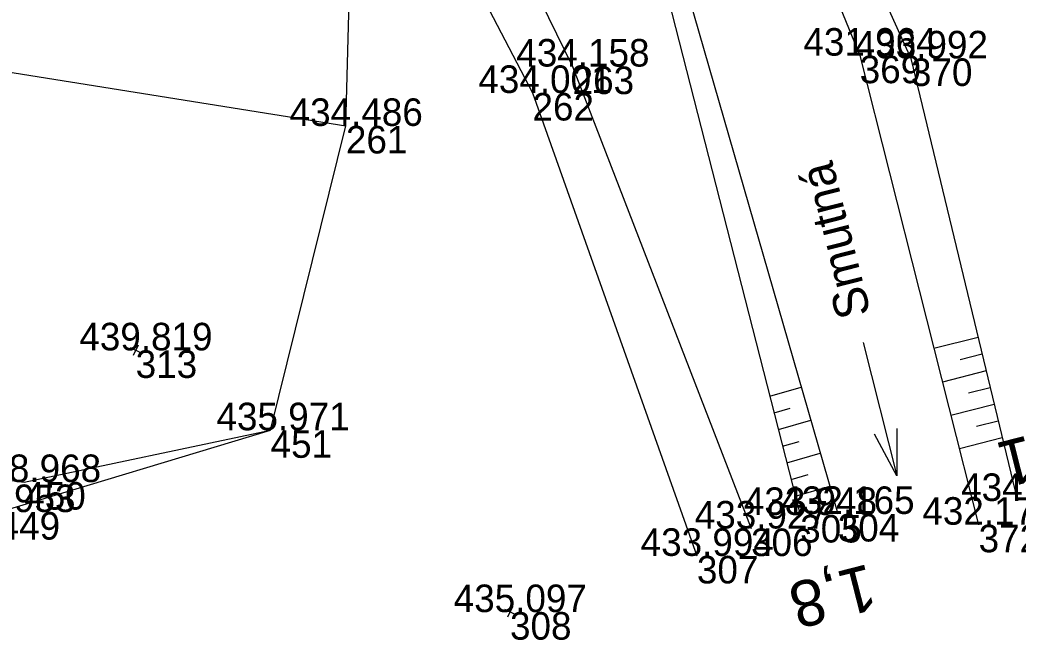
# Model space of a CAD drawing. Extents: x -751615 to -750797, y -1114905 to -1114561.
# Drawn here: x -751174.08 to -751130.63, y -1114732.78 to -1114705.77 of the extents above; entities that cross this region are included whole.
import ezdxf

# ---------------------------------------------------------------- set-up
doc = ezdxf.new("R2010")
doc.units = 0
for name, color, linetype in [('Vrstva 48', 7, 'Continuous'), ('Vrstva 49', 7, 'Continuous'), ('Vrstva 50', 7, 'Continuous'), ('Vrstva 51', 7, 'Continuous'), ('Vrstva 58', 7, 'Continuous'), ('Vrstva 60', 7, 'Continuous'), ('Vrstva 61', 7, 'Continuous')]:
    doc.layers.add(name, color=color, linetype=linetype)

msp = doc.modelspace()

# ---------------------------------------------------------------- linework, layer by layer
at = {"layer": 'Vrstva 48'}
for p, q in [((-751132.368, -1114719.605), (-751134.286, -1114720.091)), ((-751132.193, -1114720.334), (-751133.147, -1114720.576)), ((-751132.018, -1114721.064), (-751133.918, -1114721.545)), ((-751141.434, -1114722.157), (-751140.07, -1114721.764)), ((-751131.842, -1114721.793), (-751132.788, -1114722.033)), ((-751141.248, -1114722.884), (-751140.555, -1114722.684)), ((-751131.667, -1114722.522), (-751133.549, -1114722.999)), ((-751141.063, -1114723.611), (-751139.654, -1114723.205)), ((-751131.492, -1114723.252), (-751132.428, -1114723.489)), ((-751140.877, -1114724.338), (-751140.162, -1114724.132)), ((-751131.317, -1114723.981), (-751133.18, -1114724.453)), ((-751140.691, -1114725.065), (-751139.239, -1114724.647)), ((-751140.505, -1114725.792), (-751139.768, -1114725.58)), ((-751140.32, -1114726.519), (-751138.823, -1114726.088))]:
    msp.add_line(p, q, dxfattribs=at)
at = {"layer": 'Vrstva 49'}
for p, q in [((-751186.41, -1114706.153), (-751159.892, -1114710.39)), ((-751163.172, -1114723.646), (-751159.892, -1114710.39)), ((-751168.821, -1114720.276), (-751169.271, -1114720.056)), ((-751168.936, -1114719.941), (-751169.156, -1114720.391)), ((-751152.522, -1114731.677), (-751152.972, -1114731.457)), ((-751152.637, -1114731.342), (-751152.857, -1114731.792))]:
    msp.add_line(p, q, dxfattribs=at)
for points in [[(-751159.583, -1114669.179), (-751152.304, -1114674.09), (-751146.04, -1114682.559), (-751140.899, -1114695.046), (-751135.289, -1114707.45), (-751130.657, -1114726.726)], [(-751160.409, -1114669.901), (-751154.232, -1114677.23), (-751146.679, -1114684.603), (-751142.986, -1114693.954), (-751137.521, -1114707.329), (-751132.342, -1114727.761)], [(-751159.892, -1114710.39), (-751159.564, -1114697.887), (-751162.611, -1114687.691), (-751171.305, -1114676.437), (-751182.896, -1114671.724), (-751191.58, -1114672.907), (-751197.985, -1114678.047), (-751212.472, -1114698.152), (-751234.949, -1114713.279), (-751244.9, -1114718.575)], [(-751166.835, -1114672.143), (-751156.612, -1114681.118), (-751149.576, -1114689.282), (-751145.388, -1114703.319), (-751138.476, -1114727.292)], [(-751168.436, -1114673.733), (-751158.526, -1114682.859), (-751153.413, -1114687.89), (-751146.017, -1114704.22), (-751140.111, -1114727.336)], [(-751205.217, -1114723.182), (-751190.613, -1114723.681), (-751173.898, -1114725.903), (-751163.172, -1114723.646)], [(-751204.754, -1114724.609), (-751190.638, -1114725.023), (-751175.014, -1114727.21), (-751163.172, -1114723.646)]]:
    msp.add_lwpolyline(points, dxfattribs=at)
at = {"layer": 'Vrstva 50'}
for points in [[(-751160.409, -1114669.901), (-751154.232, -1114677.23), (-751146.679, -1114684.603), (-751142.986, -1114693.954), (-751137.521, -1114707.329), (-751132.342, -1114727.761)], [(-751166.835, -1114672.143), (-751156.612, -1114681.118), (-751149.576, -1114689.282), (-751145.388, -1114703.319), (-751138.476, -1114727.292)]]:
    msp.add_lwpolyline(points, dxfattribs=at)
at = {"layer": 'Vrstva 51'}
for points in [[(-751179.332, -1114665.61), (-751169.189, -1114674.547), (-751160.093, -1114686.607), (-751155.976, -1114695.63), (-751150.02, -1114707.804), (-751142.251, -1114727.926)], [(-751180.281, -1114667.838), (-751171.305, -1114676.437), (-751162.611, -1114687.691), (-751158.117, -1114696.777), (-751151.768, -1114708.954), (-751144.608, -1114729.118)]]:
    msp.add_lwpolyline(points, dxfattribs=at)
at = {"layer": 'Vrstva 58'}
msp.add_line((-751137.377, -1114719.821), (-751135.903, -1114725.637), dxfattribs=at)
msp.add_lwpolyline([(-751135.91, -1114723.575), (-751135.903, -1114725.637), (-751136.879, -1114723.821)], dxfattribs=at)
at = {"layer": 'Vrstva 60'}
for p, q in [((-751137.521, -1114707.329), (-751137.521, -1114707.329)), ((-751135.289, -1114707.45), (-751135.289, -1114707.45)), ((-751150.02, -1114707.804), (-751150.02, -1114707.804)), ((-751151.768, -1114708.954), (-751151.768, -1114708.954)), ((-751159.892, -1114710.39), (-751159.892, -1114710.39)), ((-751169.046, -1114720.166), (-751169.046, -1114720.166)), ((-751163.172, -1114723.646), (-751163.172, -1114723.646)), ((-751173.898, -1114725.903), (-751173.898, -1114725.903)), ((-751130.657, -1114726.726), (-751130.657, -1114726.726)), ((-751140.111, -1114727.336), (-751140.111, -1114727.336)), ((-751138.476, -1114727.292), (-751138.476, -1114727.292)), ((-751142.251, -1114727.926), (-751142.251, -1114727.926)), ((-751132.342, -1114727.761), (-751132.342, -1114727.761)), ((-751144.608, -1114729.118), (-751144.608, -1114729.118)), ((-751152.747, -1114731.567), (-751152.747, -1114731.567))]:
    msp.add_line(p, q, dxfattribs=at)

# ---------------------------------------------------------------- texts
at = {"layer": 'Vrstva 48'}
for s, rotation, p in [('2,1', 194.2235, (-751128.029, -1114723.307)), ('1,8', 194.3321, (-751137.132, -1114729.457))]:
    msp.add_text(s, height=2, rotation=rotation, dxfattribs=at).set_placement(p)
at = {"layer": 'Vrstva 58'}
msp.add_text('Smutná', height=1.5, rotation=104.2235, dxfattribs=at).set_placement((-751137.027, -1114718.559))
at = {"layer": 'Vrstva 60'}
for s, p in [('369', (-751137.521, -1114708.529)), ('370', (-751135.289, -1114708.65)), ('263', (-751150.02, -1114709.004)), ('262', (-751151.768, -1114710.154)), ('261', (-751159.892, -1114711.59)), ('313', (-751169.046, -1114721.366)), ('451', (-751163.172, -1114724.846)), ('450', (-751173.898, -1114727.103)), ('449', (-751175.014, -1114728.41)), ('305', (-751140.111, -1114728.536)), ('304', (-751138.476, -1114728.492)), ('306', (-751142.251, -1114729.126)), ('372', (-751132.342, -1114728.961)), ('307', (-751144.608, -1114730.318)), ('308', (-751152.747, -1114732.767))]:
    msp.add_text(s, height=1.2, dxfattribs=at).set_placement(p)
at = {"layer": 'Vrstva 61'}
for s, p in [('431.964', (-751139.972, -1114707.329)), ('433.992', (-751137.737, -1114707.45)), ('434.158', (-751152.474, -1114707.804)), ('434.001', (-751154.125, -1114708.954)), ('434.486', (-751162.344, -1114710.39)), ('439.819', (-751171.5, -1114720.166)), ('435.971', (-751165.529, -1114723.646)), ('438.968', (-751176.352, -1114725.903)), ('434.292', (-751133.105, -1114726.726)), ('439.953', (-751177.466, -1114727.21)), ('433.948', (-751142.565, -1114727.336)), ('432.165', (-751140.932, -1114727.292)), ('433.927', (-751144.703, -1114727.926)), ('432.174', (-751134.793, -1114727.761)), ('433.994', (-751147.059, -1114729.118)), ('435.097', (-751155.199, -1114731.567))]:
    msp.add_text(s, height=1.2, dxfattribs=at).set_placement(p)

doc.saveas('drawing.dxf')
